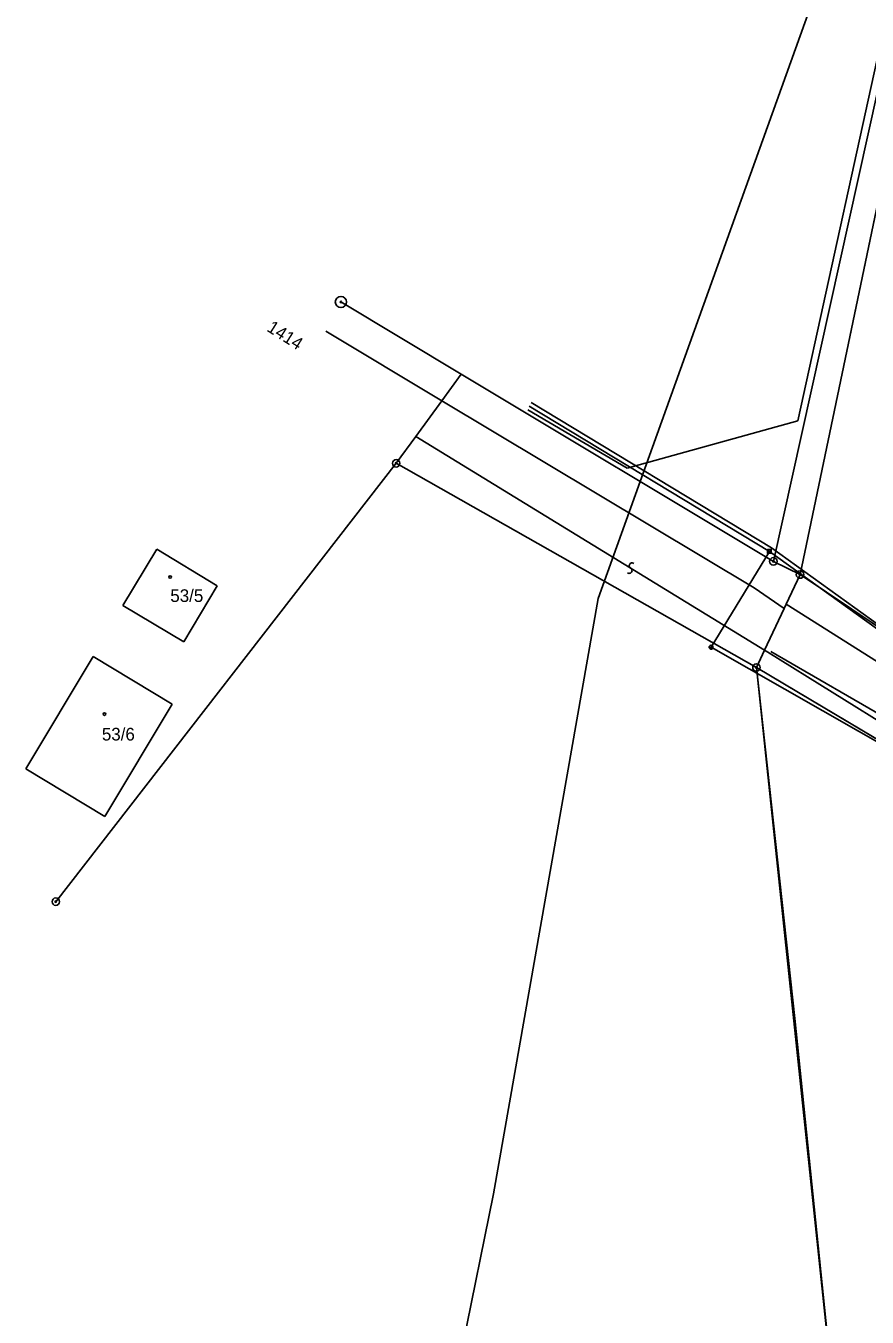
# Model space of a CAD drawing. Extents: x -469926 to -462499, y -1098642 to -1092733.
# Drawn here: x -466075 to -465962.1, y -1095421.7 to -1095248.3 of the extents above; entities that cross this region are included whole.
import ezdxf

# ---------------------------------------------------------------- set-up
doc = ezdxf.new("R2010")
doc.units = 0
for name, color, linetype in [('Vrstva 1', 7, 'Continuous'), ('Vrstva 10', 7, 'Continuous'), ('Vrstva 11', 7, 'Continuous'), ('Vrstva 12', 7, 'Continuous'), ('Vrstva 14', 7, 'Continuous'), ('Vrstva 16', 7, 'Continuous'), ('Vrstva 24', 7, 'Continuous'), ('Vrstva 25', 7, 'Continuous'), ('Vrstva 4', 7, 'Continuous'), ('Vrstva 50', 7, 'Continuous'), ('Vrstva 51', 7, 'Continuous'), ('Vrstva 8', 7, 'Continuous')]:
    doc.layers.add(name, color=color, linetype=linetype)

msp = doc.modelspace()

# ---------------------------------------------------------------- linework, layer by layer
at = {"layer": 'Vrstva 1'}
for p, q in [((-465947.43, -1095197.2), (-465974.66, -1095320.26)), ((-465971.08, -1095322.03), (-465956.67, -1095253.05)), ((-466032.73, -1095285.43), (-466016.56, -1095295.13)), ((-466019.16, -1095298.69), (-466034.75, -1095289.34)), ((-466016.56, -1095295.13), (-465974.66, -1095320.26)), ((-465977.26, -1095323.82), (-466019.16, -1095298.69)), ((-466025.31, -1095307.09), (-466071.01, -1095365.95)), ((-465976.94, -1095334.51), (-466025.31, -1095307.09)), ((-466062.01, -1095326.2), (-466057.46, -1095318.61)), ((-466057.46, -1095318.61), (-466049.32, -1095323.54)), ((-465974.66, -1095320.26), (-465971.08, -1095322.03)), ((-465971.08, -1095322.03), (-465972.95, -1095326.01)), ((-465971.08, -1095322.03), (-465939.8, -1095343)), ((-466049.32, -1095323.54), (-466053.83, -1095331.07)), ((-465973.22, -1095326.59), (-465977.26, -1095323.82)), ((-466053.83, -1095331.07), (-466062.01, -1095326.2)), ((-465972.95, -1095326.01), (-465973.22, -1095326.59)), ((-465973.22, -1095326.59), (-465975.84, -1095332.17)), ((-466075.03, -1095348.13), (-466065.99, -1095333.04)), ((-466065.99, -1095333.04), (-466055.38, -1095339.42)), ((-465975.84, -1095332.17), (-465976.94, -1095334.51)), ((-465976.94, -1095334.51), (-465934.73, -1095359.63)), ((-465971.8, -1095381.65), (-465976.94, -1095334.51)), ((-466055.38, -1095339.42), (-466064.42, -1095354.5)), ((-466064.42, -1095354.5), (-466075.03, -1095348.13)), ((-465967.24, -1095425.97), (-465971.8, -1095381.65))]:
    msp.add_line(p, q, dxfattribs=at)
at = {"layer": 'Vrstva 10'}
for points in [[(-465971.12, -1095322.11), (-465971.08, -1095322.03), (-465956.67, -1095253.05), (-465943.86, -1095198.32), (-465933.61, -1095151.26), (-465927.48, -1095140.67), (-465904.34, -1095122.76), (-465896.96, -1095106.57), (-465882.27, -1095049.78), (-465880.26, -1095017.78), (-465876.96, -1095005.81), (-465860.31, -1094932.56), (-465833.8, -1094811.76), (-465836.47, -1094811.3), (-465823.89, -1094753.98), (-465811.86, -1094688.6), (-465809.93, -1094647.11)], [(-465967.24, -1095425.97), (-465976.94, -1095334.51)]]:
    msp.add_lwpolyline(points, dxfattribs=at)
at = {"layer": 'Vrstva 11'}
for points in [[(-465896.35, -1095369.42), (-465914.62, -1095361.86), (-465916.1, -1095361.53), (-465929, -1095353.8), (-465928.92, -1095353.57), (-465933.68, -1095350.79), (-465936.9, -1095348.17), (-465935.45, -1095345.77), (-465939.8, -1095343), (-465971.08, -1095322.03)], [(-465976.94, -1095334.51), (-465934.73, -1095359.63), (-465928.97, -1095360.76), (-465916.06, -1095368.53), (-465916.11, -1095368.75), (-465911.79, -1095371.37), (-465909.32, -1095373.52)]]:
    msp.add_lwpolyline(points, dxfattribs=at)
at = {"layer": 'Vrstva 12'}
for p, q in [((-465998.17, -1095325.25), (-465962.39, -1095225.51)), ((-466012.24, -1095405.19), (-465998.17, -1095325.25)), ((-466012.24, -1095405.19), (-466033.26, -1095508.89))]:
    msp.add_line(p, q, dxfattribs=at)
at = {"layer": 'Vrstva 14'}
for p, q in [((-465971.36, -1095301.37), (-465954.93, -1095226.47)), ((-466007.65, -1095299.93), (-465994.31, -1095307.74)), ((-466007.47, -1095299.42), (-465975.2, -1095318.91)), ((-465971.36, -1095301.37), (-465994.31, -1095307.74)), ((-465975.2, -1095318.91), (-465983.03, -1095331.78)), ((-465975.45, -1095318.93), (-465975.18, -1095318.66)), ((-465975.4, -1095319.16), (-465974.95, -1095318.71)), ((-465975.2, -1095318.91), (-465944.35, -1095341.15)), ((-465975.11, -1095319.16), (-465974.95, -1095319)), ((-465982.83, -1095331.63), (-465983.24, -1095331.93)), ((-465983.24, -1095331.93), (-465982.83, -1095331.63)), ((-465983.11, -1095332.02), (-465983.07, -1095331.81)), ((-465983.03, -1095331.78), (-465950.64, -1095350.27)), ((-465982.91, -1095332), (-465982.86, -1095331.65))]:
    msp.add_line(p, q, dxfattribs=at)
msp.add_lwpolyline([(-465975.45, -1095318.66), (-465974.95, -1095318.66), (-465974.95, -1095319.16), (-465975.45, -1095319.16), (-465975.45, -1095318.66)], dxfattribs=at)
msp.add_circle((-465983.03, -1095331.78), 0.251, dxfattribs=at)
msp.add_arc((-465983.03, -1095331.78), 0.251, 216.0231, 36.0231, dxfattribs=at)
at = {"layer": 'Vrstva 16'}
for p, q in [((-466007.18, -1095298.94), (-465974.92, -1095318.43)), ((-466007.18, -1095298.94), (-465974.92, -1095318.43)), ((-466007.18, -1095298.94), (-465974.92, -1095318.43)), ((-465974.92, -1095318.43), (-465950.73, -1095335.87)), ((-465974.92, -1095318.43), (-465950.73, -1095335.87)), ((-465974.92, -1095318.43), (-465950.73, -1095335.87))]:
    msp.add_line(p, q, dxfattribs=at)
at = {"layer": 'Vrstva 24'}
for centre, radius in [((-466032.73, -1095285.43), 0.75), ((-466032.73, -1095285.43), 0.1), ((-466025.31, -1095307.09), 0.5), ((-466025.31, -1095307.09), 0.1), ((-465974.66, -1095320.26), 0.5), ((-465974.66, -1095320.26), 0.1), ((-465971.08, -1095322.03), 0.5), ((-465971.08, -1095322.03), 0.1), ((-465976.94, -1095334.51), 0.5), ((-465976.94, -1095334.51), 0.1), ((-466071.01, -1095365.95), 0.5), ((-466071.01, -1095365.95), 0.1)]:
    msp.add_circle(centre, radius, dxfattribs=at)
at = {"layer": 'Vrstva 25'}
for centre in [(-466055.66, -1095322.36), (-466064.47, -1095340.76)]:
    msp.add_circle(centre, 0.175, dxfattribs=at)
at = {"layer": 'Vrstva 4'}
for p, q in [((-466019.16, -1095298.69), (-466016.56, -1095295.13)), ((-466022.68, -1095303.5), (-466019.16, -1095298.69)), ((-466025.31, -1095307.09), (-466022.68, -1095303.5)), ((-466022.68, -1095303.5), (-465975.84, -1095332.17)), ((-465933.68, -1095350.79), (-465972.95, -1095326.01)), ((-465975.42, -1095332.43), (-465975.84, -1095332.17)), ((-465930.46, -1095360.43), (-465975.42, -1095332.43))]:
    msp.add_line(p, q, dxfattribs=at)
at = {"layer": 'Vrstva 51'}
for centre, radius, start, end in [((-465993.64, -1095320.83), 0.376, 53.6704, 239.9815), ((-465994.01, -1095321.49), 0.377, 232.9943, 60.6575)]:
    msp.add_arc(centre, radius, start, end, dxfattribs=at)
at = {"layer": 'Vrstva 8'}
msp.add_line((-465974.98, -1095332.37), (-465907.89, -1095371.27), dxfattribs=at)

# ---------------------------------------------------------------- texts
at = {"layer": 'Vrstva 50'}
msp.add_text('1414', height=1.7, rotation=327.618, dxfattribs=at).set_placement((-466042.79, -1095289.25))
for s, p in [('53/5', (-466055.63, -1095325.71)), ('53/6', (-466064.82, -1095344.31))]:
    msp.add_text(s, height=1.7, dxfattribs=at).set_placement(p)

doc.saveas('drawing.dxf')
